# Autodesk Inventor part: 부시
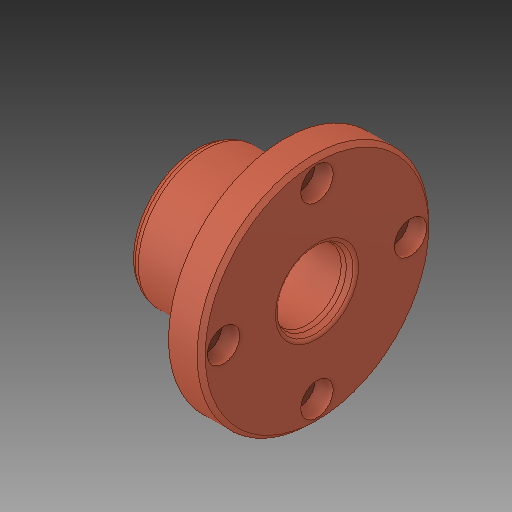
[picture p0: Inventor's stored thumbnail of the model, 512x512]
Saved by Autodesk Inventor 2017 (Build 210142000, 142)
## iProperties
Created: 2024-09
Part Number: 부시
Material: 일반
Document SubType Name: Modeling
Designer: MRC
Density: 1 g/cm^3
Appearance: 기본값
Author: jhkim
Sending System: Autodesk Inventor 2025
Preprocessor: ST-DEVELOPER v20
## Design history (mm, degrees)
feature "솔리드1"
node "솔리드2"
